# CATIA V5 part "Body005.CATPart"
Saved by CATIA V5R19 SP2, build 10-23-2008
Part number: Body005
Definition: design
Nomenclature: Body005
Source: Unknown
Bounding box of the stored display mesh (mm): x 20.52 to 27.52, y 15.11 to 27.61, z 0 to 2
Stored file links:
  Z:\fausse table rondelle-20220905T211342Z-001\fausse table rondelle\Body005.CATPart
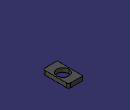
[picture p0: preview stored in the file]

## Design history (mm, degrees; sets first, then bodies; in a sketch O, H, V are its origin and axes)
AxisSystem1: origin (0, 0, 0), X (1, 0, 0), Y (0, 1, 0), Z (0, 0, 1)
Body1 "MANIFOLD_SOLID_BREP #36137" (main body)
  Solid1: solid without history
